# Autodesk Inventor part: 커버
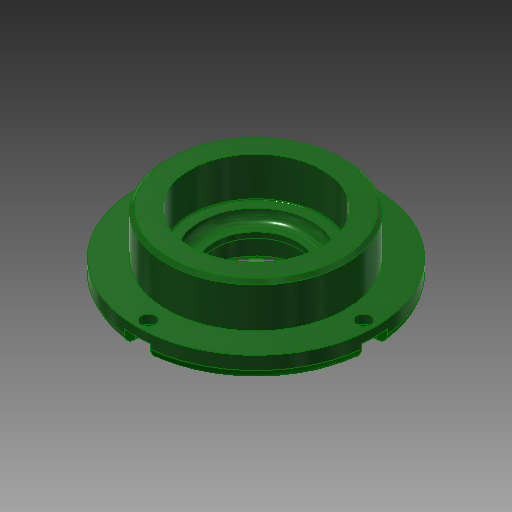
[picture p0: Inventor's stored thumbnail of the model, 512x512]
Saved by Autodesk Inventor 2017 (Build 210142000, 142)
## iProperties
Company: 한국ATC센터
Created: 2016-04
Part Number: 커버
Document SubType Name: Modeling
Designer: mdu
Density: 7.86 g/cm^3
Mass: 351.567 g
Surface Area: 161.165 cm^2
Volume: 44.7286 cm^3
Material: 강철, 연강
Appearance: 진녹색
Author: mdu
Revision Number: 1
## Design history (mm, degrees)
sketch "스케치1"
  geometry: C1 r 36 at (0, 0); 1 further point
  constraints: 1 centre point, 1 coincident
  dimensions: "d0" = 72 diameter of C1
extrude "돌출1" new body sketch "스케치1" distance "d1" = 7; taper "d2" = 0 deg
sketch "스케치2"
  geometry: C1 r 27 at (0, 0); 1 further point
  constraints: 1 centre point, 1 coincident
  dimensions: "d3" = 54 diameter of C1
extrude "돌출2" join sketch "스케치2" distance "d4" = 13; taper "d5" = 0 deg
sketch "스케치3"
  geometry: C1 r 20 at (0, 0); 1 further point
  constraints: 1 centre point, 1 coincident
  dimensions: "d6" = 40 diameter of C1
extrude "돌출3" join sketch "스케치3" distance "d7" = 5; taper "d8" = 0 deg
hole "구멍1" diameter "d11" = 25; stored, may be unused: countersink angle "d15" = 90 deg, drill point angle "d17" = 118 deg; dims "d9" = 10, "d10" = 10, "d12" = 6, "d13" = 32, "d14" = 8.3, "d16" = 8
hole "구멍2" diameter "d20" = 34; stored, may be unused: countersink angle "d24" = 90 deg, drill point angle "d26" = 0 deg; dims "d18" = 10, "d19" = 10, "d21" = 6, "d22" = 40, "d23" = 12, "d25" = 3
fillet "모깎기2" dims "d34" = 3
fillet "모깎기1" dims "d27" = 0.3
chamfer "모따기1" distance "d28" = 1; stored, may be unused: second distance "d29" = 2, angle "d30" = 45 deg
chamfer "모따기2" distance "d31" = 1.2; stored, may be unused: second distance "d32" = 2, angle "d33" = 30 deg
sketch "스케치4" dims "d35" = 65
  geometry: 3 further points
  constraints: 2 horizontal alignment, 1 coincident, 2 other
hole "구멍3" sketch "스케치4" at (32.5, 0) diameter "d36" = 4.5; stored, may be unused: countersink angle "d40" = 90 deg, drill point angle "d42" = 118 deg; dims "d37" = 6, "d38" = 8, "d39" = 4.4, "d41" = 13
sketch "스케치5"
  geometry: L1 (4, 0)-(4, 3.5); L2 (-4, 3.5)-(-4, 0); L3 (4, 3.5)-(-4, 3.5); C1 r 2.25 at (0, 0) reference; C2 r 36 at (0, -32.5) reference; A1 r 4 centre (0, 0) between (-2.037, 3.442) and (2.037, 3.442) reference; A2 r 36 centre (0, -32.5) between (2.037, 3.442) and (-2.037, 3.442) reference; 2 further points
  constraints: 6 end point, 2 horizontal alignment, 2 point on circle, 1 horizontal, 1 midpoint, 1 parallel, 1 tangent, 1 vertical, 1 vertical alignment
extrude "돌출4" cut sketch "스케치5" stored distance "d47" = 24.5; taper "d48" = 0 deg
node "솔리드1"
pattern_circular "원형 패턴1" dims angle "d44" = 360 deg
pattern_circular "원형 패턴2" dims angle "d50" = 360 deg
node "투영된 루프1"
